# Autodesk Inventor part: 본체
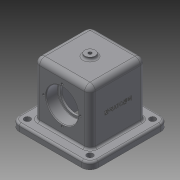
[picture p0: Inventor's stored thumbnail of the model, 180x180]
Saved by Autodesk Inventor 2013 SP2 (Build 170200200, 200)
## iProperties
Created: 2022-07
Part Number: 본체
Material: Generic
Document SubType Name: Modeling
Designer: i
Density: 1 g/cm^3
Author: i
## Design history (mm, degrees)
sketch "스케치1"
  geometry: L1 (-41, -40)-(41, -40); L2 (41, -40)-(41, 40); L3 (41, 40)-(-41, 40); L4 (-41, 40)-(-41, -40); L5 (-41, -40)-(41, 40); L6 (41, -40)-(-41, 40); 1 further point
  constraints: 12 end point, 2 midpoint, 2 parallel, 1 horizontal, 1 perpendicular
  dimensions: "d0" = 82 distance of L2.end L3.end; "d2" = 80 distance of L1.end L2.end
extrude "돌출1" new body sketch "스케치1" stored distance "d3" = 82; taper "d4" = 0 deg
sketch "스케치2"
  geometry: L1 (-17, -99)-(99, -99); L2 (99, -99)-(99, 17); L3 (99, 17)-(-17, 17); L4 (-17, 17)-(-17, -99); L5 (-17, -99)-(99, 17); L6 (99, -99)-(-17, 17); 1 further point
  constraints: 12 end point, 2 midpoint, 2 parallel, 1 horizontal, 1 perpendicular
  dimensions: "d5" = 116 distance of L3.end L2.end; "d6" = 116 distance of L2.end L1.end
extrude "돌출2" join sketch "스케치2" distance "d7" = 10; taper "d8" = 0 deg
sketch "스케치3"
  geometry: L1 (41, 40)-(-41, 40) reference; C1 r 23.5 at (0, -2); 1 further point
  constraints: 1 centre point, 1 vertical alignment
  dimensions: "d9" = 47 diameter of C1; "d10" = 42 distance from line of L1 C1.centre
extrude "돌출3" cut sketch "스케치3" distance "d11" = 17; taper "d12" = 0 deg
sketch "스케치4"
  geometry: L1 (11, -62)-(71, -62); L2 (71, -62)-(71, -20); L3 (71, -20)-(11, -20); L4 (11, -20)-(11, -62); L5 (11, -62)-(71, -20); L6 (71, -62)-(11, -20); 1 further point
  constraints: 12 end point, 2 midpoint, 2 parallel, 1 horizontal, 1 perpendicular
  dimensions: "d13" = 60 distance of L3.end L2.end; "d14" = 42 distance of L2.end L1.end
extrude "돌출4" cut sketch "스케치4" distance "d15" = 80; taper "d16" = 0 deg
sketch "스케치5"
  geometry: C1 r 23.5 at (0, 0) reference; C2 r 20 at (0, 0); 1 further point
  constraints: 1 centre point, 1 coincident
  dimensions: "d17" = 40 diameter of C2
extrude "돌출5" cut sketch "스케치5" stored distance "d18" = 80; taper "d19" = 0 deg
fillet "모깎기1" dims "d20" = 0.6
fillet "모깎기2" dims "d21" = 3
fillet "모깎기3" dims "d22" = 3
chamfer "모따기1" distance "d23" = 1; stored, may be unused: second distance "d24" = 2, angle "d25" = 45 deg
fillet "모깎기4" dims "d26" = 8
fillet "모깎기5" dims "d27" = 8
fillet "모깎기6" dims "d28" = 12
fillet "모깎기7" dims "d29" = 3
sketch "스케치6"
  geometry: C1 r 4.5 at (-5, 87); C2 r 4.5 at (87, 87); C3 r 4.5 at (87, -5); C4 r 4.5 at (-5, -5); A1 r 12 centre (-5, 87) between (-5, 99) and (-17, 87) reference; A2 r 12 centre (-5, -5) between (-17, -5) and (-5, -17) reference; A3 r 12 centre (87, -5) between (87, -17) and (99, -5) reference; A4 r 12 centre (87, 87) between (99, 87) and (87, 99) reference; 1 further point
  constraints: 4 centre point, 4 coincident
  dimensions: "d30" = 9 diameter of C1; "d31" = 9 diameter of C2; "d33" = 9 diameter of C3; "d34" = 9 diameter of C4
extrude "돌출6" cut sketch "스케치6" stored distance "d35" = 80; taper "d36" = 0 deg
fillet "모깎기8" dims "d37" = 3
sketch "스케치7"
  geometry: C1 r 7.5 at (33, 33); 1 further point
  constraints: 1 centre point, 1 coincident
  dimensions: "d38" = 15 diameter of C1
extrude "돌출7" join sketch "스케치7" distance "d39" = 4; taper "d40" = 0 deg
sketch "스케치8"
  geometry: C1 r 7.5 at (0, 0) reference; 1 further point
  constraints: 1 coincident
hole "구멍1" sketch "스케치8" at (0, 0) diameter "d41" = 4.917; stored, may be unused: countersink angle "d45" = 90 deg, drill point angle "d47" = 118 deg; dims "d42" = 6, "d43" = 4, "d44" = 2, "d46" = 8
sketch "스케치9"
  geometry: C1 r 24.5 at (0, -2) reference; 2 further points
  constraints: 1 vertical alignment
  dimensions: "d48" = 27 distance of C1.centre point (0, 25)
hole "구멍2" sketch "스케치9" at (0, 25) diameter "d49" = 3.242; stored, may be unused: countersink angle "d53" = 90 deg, drill point angle "d55" = 118 deg; dims "d50" = 8, "d51" = 4, "d52" = 2, "d54" = 10
fillet "모깎기9" dims "d59" = 3
sketch "스케치10"
  geometry: L1 (79, -82)-(-13, -82) reference; 2 further points
  constraints: 1 vertical alignment, 1 other
  dimensions: "d60" = 48 distance from line of L1 point (33, -34)
feature "엠보싱1" sketch "스케치10" dims "d0" = 82, "d2" = 80, "d9" = 47, "d10" = 42, "d61" = 0.5, "d62" = 0
node "솔리드1"
mirror "대칭1"
pattern_circular "원형 패턴1" dims angle "d57" = 360 deg
mirror "대칭2"
